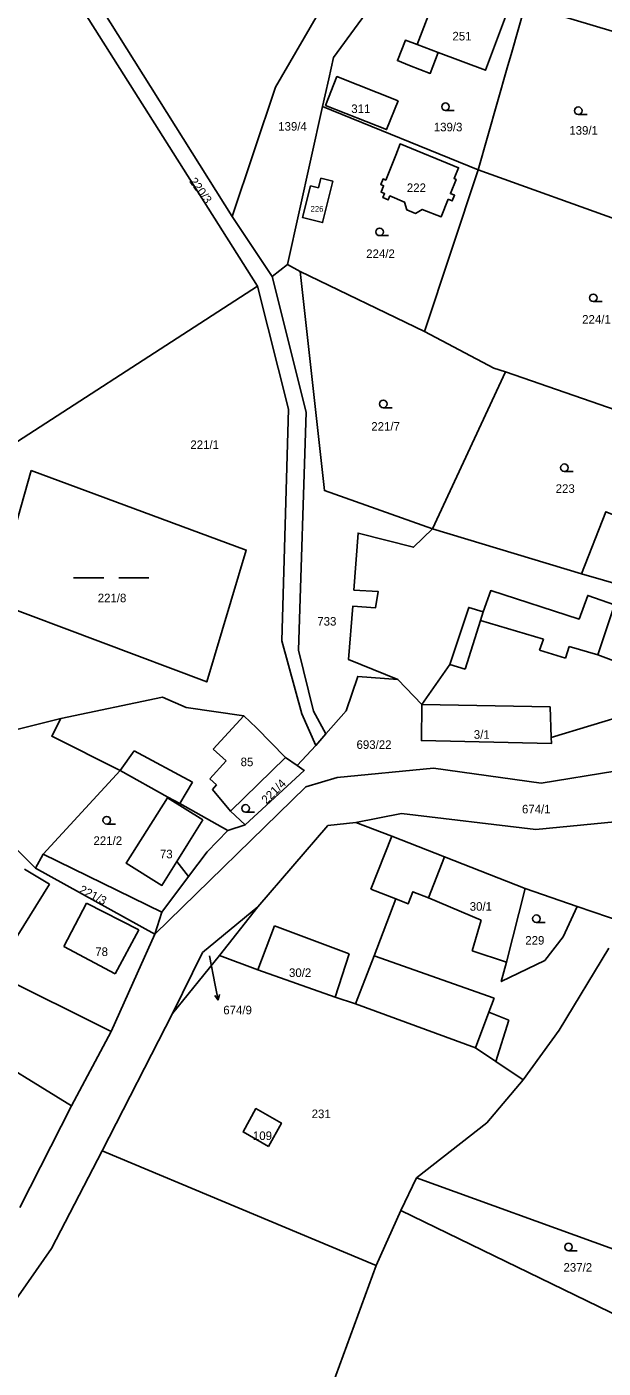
# Model space of a CAD drawing. Extents: x -747333 to -743907, y -1134120 to -1130051.
# Drawn here: x -746642.5 to -746528, y -1132212.3 to -1131946.1 of the extents above; entities that cross this region are included whole.
import ezdxf

# ---------------------------------------------------------------- set-up
doc = ezdxf.new("R2010")
doc.units = 0
for name, color, linetype in [('Hranice parcel', 7, 'Continuous'), ('Parcelní čísla', 7, 'Continuous'), ('Pop  PČ popisy', 7, 'Continuous'), ('Vnitřní kresba', 7, 'Continuous'), ('Značky kultur', 7, 'Continuous')]:
    doc.layers.add(name, color=color, linetype=linetype)

msp = doc.modelspace()

# ---------------------------------------------------------------- linework, layer by layer
at = {"layer": 'Hranice parcel'}
for p, q in [((-746637.77, -1131926.3), (-746601.69, -1131983.7)), ((-746596.68, -1131997.54), (-746638.63, -1131931.22)), ((-746543.47, -1131941.76), (-746546.13, -1131951.07)), ((-746546.13, -1131951.07), (-746547.04, -1131954.23)), ((-746547.04, -1131954.23), (-746552.82, -1131974.44)), ((-746583.19, -1131959.53), (-746583.72, -1131961.89)), ((-746583.72, -1131961.89), (-746590.71, -1131993.24)), ((-746552.82, -1131974.44), (-746583.72, -1131961.89)), ((-746563.47, -1132006.55), (-746552.82, -1131974.44)), ((-746552.82, -1131974.44), (-746522.94, -1131985.19)), ((-746593.75, -1131995.59), (-746601.69, -1131983.7)), ((-746593.75, -1131995.59), (-746590.71, -1131993.24)), ((-746588.16, -1131994.6), (-746590.71, -1131993.24)), ((-746588.16, -1131994.6), (-746563.47, -1132006.55)), ((-746561.87, -1132045.71), (-746547.41, -1132014.55)), ((-746517.52, -1132024.84), (-746547.41, -1132014.55)), ((-746561.87, -1132045.71), (-746532.26, -1132054.61)), ((-746568.79, -1132075.6), (-746564.02, -1132080.55)), ((-746674.91, -1132092.97), (-746635.72, -1132083.37)), ((-746596.87, -1132085.19), (-746599.39, -1132082.82)), ((-746591.11, -1132091.08), (-746596.87, -1132085.19)), ((-746585.09, -1132088.73), (-746583.05, -1132086.4)), ((-746588.76, -1132092.67), (-746585.09, -1132088.73)), ((-746591.11, -1132091.08), (-746588.76, -1132092.67)), ((-746623.94, -1132093.67), (-746639.26, -1132110.3)), ((-746623.94, -1132093.67), (-746614.46, -1132098.94)), ((-746614.46, -1132098.94), (-746614.54, -1132099.07)), ((-746602.53, -1132105.58), (-746599.1, -1132104.47)), ((-746640.76, -1132113.05), (-746644.51, -1132109.35)), ((-746639.26, -1132110.3), (-746640.76, -1132113.05)), ((-746639.26, -1132110.3), (-746615.65, -1132121.76)), ((-746559.47, -1132110.81), (-746562.67, -1132118.96)), ((-746543.47, -1132117.1), (-746559.47, -1132110.81)), ((-746617.06, -1132126.14), (-746640.76, -1132113.05)), ((-746612.7, -1132111.76), (-746610.34, -1132114.69)), ((-746615.65, -1132121.76), (-746610.34, -1132114.69)), ((-746533.15, -1132120.64), (-746543.47, -1132117.1)), ((-746596.59, -1132120.74), (-746604.23, -1132130.37)), ((-746523.8, -1132123.84), (-746533.15, -1132120.64)), ((-746617.06, -1132126.14), (-746615.65, -1132121.76)), ((-746659.43, -1132128.69), (-746625.72, -1132145.44)), ((-746604.23, -1132130.37), (-746613.53, -1132141.89)), ((-746577.16, -1132139.99), (-746553.33, -1132148.74)), ((-746613.53, -1132141.89), (-746627.53, -1132169.14)), ((-746633.63, -1132160.23), (-746625.72, -1132145.44)), ((-746633.63, -1132160.23), (-746643.87, -1132180.43)), ((-746627.53, -1132169.14), (-746573.08, -1132191.94)), ((-746568.17, -1132180.98), (-746565.04, -1132174.52)), ((-746573.08, -1132191.94), (-746568.17, -1132180.98)), ((-746508.81, -1132209.8), (-746568.17, -1132180.98))]:
    msp.add_line(p, q, dxfattribs=at)
for points in [[(-746601.69, -1131983.7), (-746593.05, -1131958.05), (-746576.43, -1131929.41)], [(-746563.57, -1131935.97), (-746571.75, -1131938.7), (-746581.53, -1131952.14), (-746582.49, -1131956.4), (-746583.19, -1131959.53)], [(-746551.26, -1131942.03), (-746547.16, -1131943.56), (-746551.34, -1131954.67), (-746560.74, -1131951.14), (-746562.32, -1131955.31), (-746566.43, -1131953.71), (-746568.84, -1131952.76), (-746567.28, -1131948.71), (-746564.91, -1131949.57), (-746561.44, -1131940.34), (-746555.51, -1131942.57), (-746554.83, -1131940.71), (-746551.26, -1131942.03)], [(-746513.04, -1131950.81), (-746536.83, -1131943.73), (-746543.47, -1131941.76)], [(-746568.74, -1131960.75), (-746571.01, -1131966.47), (-746583.14, -1131961.66), (-746580.87, -1131955.94), (-746568.74, -1131960.75)], [(-746558.77, -1131980.29), (-746560.18, -1131983.8), (-746563.92, -1131982.3), (-746565.28, -1131983.08), (-746566.96, -1131982.4), (-746567.42, -1131980.89), (-746570.33, -1131979.62), (-746570.68, -1131980.42), (-746571.75, -1131979.95), (-746571.41, -1131979.15), (-746572.11, -1131978.85), (-746571.61, -1131977.61), (-746572.17, -1131977.38), (-746571.72, -1131976.26), (-746571.16, -1131976.49), (-746569.17, -1131971.54), (-746568.31, -1131969.31), (-746556.71, -1131974.04), (-746557.6, -1131976.19), (-746557.19, -1131976.35), (-746558.32, -1131979.15), (-746557.5, -1131979.48), (-746557.96, -1131980.63), (-746558.77, -1131980.29)], [(-746586.1, -1131977.6), (-746587.73, -1131983.9), (-746583.74, -1131984.9), (-746581.67, -1131976.71), (-746584.07, -1131976.1), (-746584.55, -1131977.99), (-746586.1, -1131977.6)], [(-746583.05, -1132086.4), (-746585.55, -1132081.91), (-746588.49, -1132069.81), (-746587.02, -1132022.55), (-746593.75, -1131995.59)], [(-746588.16, -1131994.6), (-746583.35, -1132038.1), (-746561.87, -1132045.71)], [(-746674.91, -1132092.97), (-746654.17, -1132083.68), (-746655.72, -1132049.5), (-746655.89, -1132035.79), (-746596.68, -1131997.54)], [(-746596.68, -1131997.54), (-746590.52, -1132021.94), (-746591.81, -1132067.9), (-746587.84, -1132082.41), (-746585.09, -1132088.73)], [(-746547.41, -1132014.55), (-746549.71, -1132013.83), (-746563.47, -1132006.55)], [(-746641.62, -1132034.15), (-746598.91, -1132049.91), (-746606.74, -1132076.1), (-746649.06, -1132060.2), (-746641.62, -1132034.15)], [(-746521.13, -1132044.79), (-746527.47, -1132042.31), (-746532.26, -1132054.61)], [(-746561.87, -1132045.71), (-746565.66, -1132049.36), (-746576.68, -1132046.55), (-746577.49, -1132057.87), (-746572.66, -1132058.15), (-746573.2, -1132061.38), (-746577.72, -1132061.05), (-746578.6, -1132071.62), (-746568.79, -1132075.6)], [(-746532.26, -1132054.61), (-746523.53, -1132057.16), (-746506.99, -1132064.63), (-746500.33, -1132067.94)], [(-746514.69, -1132079.97), (-746518.97, -1132074.45), (-746529.02, -1132070.74), (-746525.69, -1132060.77), (-746531.05, -1132058.91), (-746532.75, -1132063.63), (-746550.3, -1132057.95), (-746551.82, -1132062.16), (-746554.68, -1132061.31), (-746558.47, -1132072.6), (-746564.02, -1132080.55)], [(-746500.33, -1132067.94), (-746525.66, -1132093.79), (-746540.32, -1132096.18), (-746561.68, -1132093.18), (-746580.81, -1132095.03), (-746587.06, -1132096.88), (-746617.06, -1132126.14)], [(-746568.79, -1132075.6), (-746576.74, -1132074.99), (-746579.07, -1132081.82), (-746583.05, -1132086.4)], [(-746599.39, -1132082.82), (-746610.83, -1132081.15), (-746615.53, -1132079.14), (-746635.72, -1132083.37)], [(-746564.02, -1132080.55), (-746564.09, -1132087.72), (-746538.22, -1132088.29), (-746538.28, -1132087.14), (-746514.69, -1132079.97)], [(-746635.72, -1132083.37), (-746637.54, -1132086.86), (-746623.94, -1132093.67)], [(-746599.1, -1132104.47), (-746602.03, -1132101.77), (-746591.11, -1132091.08)], [(-746599.1, -1132104.47), (-746587.37, -1132093.67), (-746588.76, -1132092.67)], [(-746577.11, -1132104.01), (-746568.02, -1132102.18), (-746541.34, -1132105.39), (-746522.96, -1132103.62), (-746512.89, -1132094.09)], [(-746614.54, -1132099.07), (-746622.78, -1132112.05), (-746615.64, -1132116.49), (-746612.7, -1132111.76)], [(-746602.53, -1132105.58), (-746612.12, -1132100.24), (-746614.46, -1132098.94)], [(-746577.11, -1132104.01), (-746582.65, -1132104.57), (-746596.59, -1132120.74)], [(-746559.47, -1132110.81), (-746569.99, -1132106.68), (-746577.11, -1132104.01)], [(-746610.34, -1132114.69), (-746606.66, -1132109.79), (-746602.53, -1132105.58)], [(-746562.67, -1132118.96), (-746565.79, -1132117.73), (-746566.72, -1132120.11), (-746569.14, -1132119.16), (-746573.49, -1132130.45), (-746577.16, -1132139.99)], [(-746533.15, -1132120.64), (-746535.92, -1132126.71), (-746539.58, -1132131.37), (-746548.21, -1132135.57), (-746547.18, -1132131.68), (-746543.47, -1132117.1)], [(-746613.53, -1132141.89), (-746607.56, -1132129.82), (-746596.59, -1132120.74)], [(-746625.72, -1132145.44), (-746620.55, -1132133.99), (-746617.06, -1132126.14)], [(-746543.9, -1132155.07), (-746536.7, -1132145.21), (-746526.85, -1132128.93)], [(-746604.23, -1132130.37), (-746596.59, -1132133.25), (-746581.21, -1132138.68), (-746577.16, -1132139.99)], [(-746666.94, -1132138.69), (-746653.23, -1132148.18), (-746633.63, -1132160.23)], [(-746553.33, -1132148.74), (-746549.28, -1132151.46), (-746543.9, -1132155.07)], [(-746565.04, -1132174.52), (-746551.09, -1132163.59), (-746543.9, -1132155.07)], [(-746594.5, -1132168.32), (-746591.89, -1132163.64), (-746596.96, -1132160.78), (-746599.53, -1132165.41), (-746594.5, -1132168.32)], [(-746627.53, -1132169.14), (-746637.59, -1132188.53), (-746647.21, -1132202.3), (-746673.25, -1132224.8), (-746705.52, -1132254.75)], [(-746506.79, -1132206.34), (-746525.9, -1132188.66), (-746565.04, -1132174.52)], [(-746594.73, -1132254.38), (-746582.55, -1132217.69), (-746573.08, -1132191.94)]]:
    msp.add_lwpolyline(points, dxfattribs=at)
at = {"layer": 'Pop  PČ popisy'}
for p, q in [((-746606.23, -1132130.48), (-746605.05, -1132136.29)), ((-746605.05, -1132136.29), (-746604.477, -1132139.236)), ((-746604.477, -1132139.236), (-746605.16, -1132138.348)), ((-746604.477, -1132139.236), (-746604.177, -1132138.157))]:
    msp.add_line(p, q, dxfattribs=at)
at = {"layer": 'Vnitřní kresba'}
for p, q in [((-746564.91, -1131949.57), (-746560.74, -1131951.14)), ((-746551.82, -1132062.16), (-746552.36, -1132063.88)), ((-746552.36, -1132063.88), (-746555.38, -1132073.53)), ((-746539.82, -1132067.57), (-746552.36, -1132063.88)), ((-746540.61, -1132069.81), (-746539.82, -1132067.57)), ((-746535.43, -1132071.36), (-746540.61, -1132069.81)), ((-746534.75, -1132069.06), (-746535.43, -1132071.36)), ((-746529.02, -1132070.74), (-746534.75, -1132069.06)), ((-746555.38, -1132073.53), (-746558.47, -1132072.6)), ((-746564.02, -1132080.55), (-746538.53, -1132081.03)), ((-746538.53, -1132081.03), (-746538.28, -1132087.14)), ((-746599.39, -1132082.82), (-746605.49, -1132089.45)), ((-746605.49, -1132089.45), (-746602.86, -1132091.75)), ((-746621.16, -1132089.74), (-746623.94, -1132093.67)), ((-746609.59, -1132095.98), (-746621.16, -1132089.74)), ((-746602.86, -1132091.75), (-746606.14, -1132095.3)), ((-746612.12, -1132100.24), (-746609.59, -1132095.98)), ((-746606.14, -1132095.3), (-746604.8, -1132096.54)), ((-746604.8, -1132096.54), (-746605.63, -1132097.45)), ((-746605.63, -1132097.45), (-746602.03, -1132101.77)), ((-746614.54, -1132099.07), (-746607.55, -1132103.47)), ((-746607.55, -1132103.47), (-746610.49, -1132108.2)), ((-746569.99, -1132106.68), (-746574.12, -1132117.2)), ((-746612.7, -1132111.76), (-746610.49, -1132108.2)), ((-746637.99, -1132116.23), (-746642.98, -1132113.24)), ((-746646.97, -1132130.75), (-746637.99, -1132116.23)), ((-746569.14, -1132119.16), (-746574.12, -1132117.2)), ((-746635.14, -1132128.6), (-746630.61, -1132120)), ((-746630.61, -1132120), (-746620.25, -1132125.3)), ((-746562.67, -1132118.96), (-746552.2, -1132123.39)), ((-746552.2, -1132123.39), (-746553.97, -1132129.48)), ((-746620.25, -1132125.3), (-746624.93, -1132134.05)), ((-746596.59, -1132133.25), (-746593.27, -1132124.5)), ((-746593.27, -1132124.5), (-746578.44, -1132130.04)), ((-746624.93, -1132134.05), (-746635.14, -1132128.6)), ((-746578.44, -1132130.04), (-746581.21, -1132138.68)), ((-746549.62, -1132138.87), (-746573.49, -1132130.45)), ((-746553.97, -1132129.48), (-746547.18, -1132131.68)), ((-746550.66, -1132141.62), (-746549.62, -1132138.87)), ((-746553.33, -1132148.74), (-746550.66, -1132141.62)), ((-746546.74, -1132143.19), (-746550.66, -1132141.62)), ((-746549.28, -1132151.46), (-746546.74, -1132143.19))]:
    msp.add_line(p, q, dxfattribs=at)
at = {"layer": 'Značky kultur'}
for p, q in [((-746559.303, -1131962.67), (-746557.553, -1131962.67)), ((-746532.923, -1131963.47), (-746531.173, -1131963.47)), ((-746572.403, -1131987.51), (-746570.653, -1131987.51)), ((-746529.933, -1132000.6), (-746528.183, -1132000.6)), ((-746571.663, -1132021.66), (-746569.913, -1132021.66)), ((-746535.683, -1132034.33), (-746533.933, -1132034.33)), ((-746633.219, -1132055.42), (-746627.219, -1132055.42)), ((-746624.219, -1132055.42), (-746618.219, -1132055.42)), ((-746599.013, -1132101.93), (-746597.263, -1132101.93)), ((-746626.623, -1132104.29), (-746624.873, -1132104.29)), ((-746541.233, -1132123.84), (-746539.483, -1132123.84)), ((-746534.863, -1132188.99), (-746533.113, -1132188.99))]:
    msp.add_line(p, q, dxfattribs=at)
for centre in [(-746559.303, -1131961.92), (-746532.923, -1131962.72), (-746572.403, -1131986.76), (-746529.933, -1131999.85), (-746571.663, -1132020.91), (-746535.683, -1132033.58), (-746626.623, -1132103.54), (-746599.013, -1132101.18), (-746541.233, -1132123.09), (-746534.863, -1132188.24)]:
    msp.add_circle(centre, 0.75, dxfattribs=at)

# ---------------------------------------------------------------- texts
at = {"layer": 'Parcelní čísla'}
for s, height, p in [('251', 1.7, (-746557.924, -1131948.76)), ('311', 1.7, (-746578.024, -1131963.17)), ('139/4', 1.7, (-746592.54, -1131966.67)), ('139/3', 1.7, (-746561.63, -1131966.8)), ('139/1', 1.7, (-746534.7, -1131967.47)), ('222', 1.7, (-746566.98, -1131978.85)), ('226', 1.14, (-746586.11, -1131982.76)), ('224/2', 1.7, (-746575.06, -1131991.95)), ('224/1', 1.7, (-746532.14, -1132004.97)), ('221/7', 1.7, (-746574.05, -1132026.22)), ('221/1', 1.7, (-746610, -1132029.85)), ('223', 1.7, (-746537.41, -1132038.56)), ('221/8', 1.7, (-746628.41, -1132060.27)), ('733', 1.7, (-746584.774, -1132064.91)), ('3/1', 1.7, (-746553.68, -1132087.37)), ('693/22', 1.7, (-746576.98, -1132089.38)), ('85', 1.7, (-746600.012, -1132092.81)), ('674/1', 1.7, (-746544.103, -1132102.18)), ('221/2', 1.7, (-746629.25, -1132108.44)), ('73', 1.7, (-746616.05, -1132111.1)), ('30/1', 1.7, (-746554.49, -1132121.5)), ('229', 1.7, (-746543.45, -1132128.23)), ('78', 1.7, (-746628.9, -1132130.49)), ('30/2', 1.7, (-746590.4, -1132134.65)), ('674/9', 1.7, (-746603.46, -1132142.063)), ('231', 1.7, (-746585.9, -1132162.67)), ('109', 1.7, (-746597.57, -1132167.01)), ('237/2', 1.7, (-746535.85, -1132193.15))]:
    msp.add_text(s, height=height, dxfattribs=at).set_placement(p)
for s, rotation, p in [('220/3', 306, (-746610.307, -1131976.729)), ('221/4', 45, (-746594.868, -1132100.441)), ('221/3', 333, (-746632.266, -1132117.858))]:
    msp.add_text(s, height=1.7, rotation=rotation, dxfattribs=at).set_placement(p)

doc.saveas('drawing.dxf')
